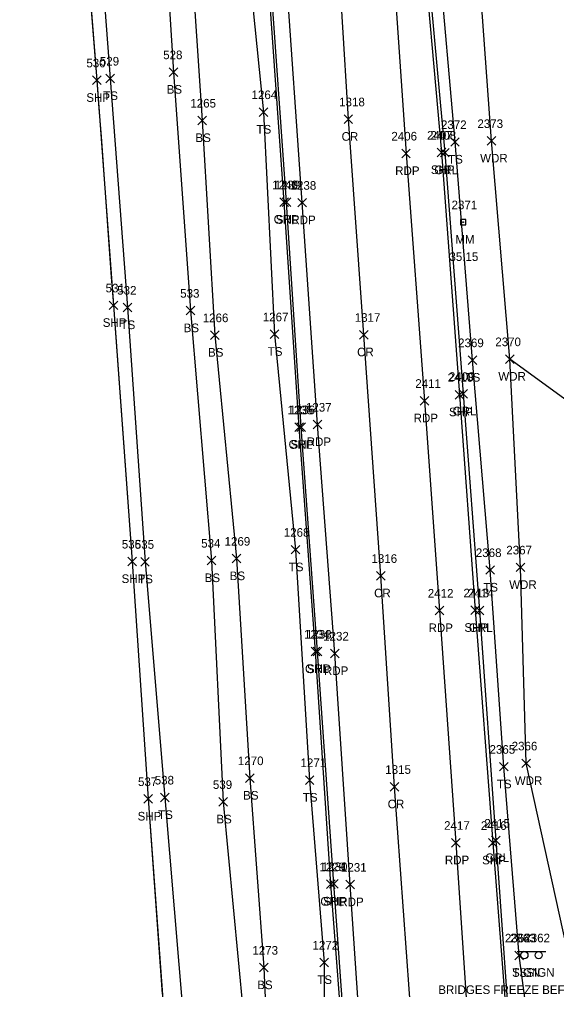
# Model space of a CAD drawing. Extents: x 1650221 to 1650634, y 244606 to 249996.
# Drawn here: x 1650231.8 to 1650356.4, y 246819.2 to 247044.4 of the extents above; entities that cross this region are included whole.
import ezdxf

# ---------------------------------------------------------------- set-up
doc = ezdxf.new("R2010")
doc.units = 0
for name, color, linetype in [('L_A', 7, 'Continuous'), ('L_I', 7, 'Continuous'), ('L_TIC', 7, 'Continuous'), ('LAWA', 7, 'Continuous'), ('LELB', 7, 'Continuous'), ('LSOGP', 7, 'Continuous'), ('P_A', 7, 'Continuous'), ('P_I', 7, 'Continuous'), ('P_TIC', 7, 'Continuous'), ('PET', 7, 'Continuous'), ('PRC', 7, 'Continuous'), ('PSP', 7, 'Continuous'), ('R_A', 7, 'Continuous'), ('R_I', 7, 'Continuous'), ('R_TIC', 7, 'Continuous'), ('RGR', 7, 'Continuous'), ('S_A', 7, 'Continuous'), ('S_C', 7, 'Continuous'), ('S_I', 7, 'Continuous'), ('SRM', 7, 'Continuous'), ('SSGN', 7, 'Continuous')]:
    doc.layers.add(name, color=color, linetype=linetype)

msp = doc.modelspace()

# ---------------------------------------------------------------- linework, layer by layer
at = {"layer": 'L_TIC'}
for points in [[(1650251.85, 247029.65), (1650253.85, 247031.65)], [(1650253.85, 247029.65), (1650251.85, 247031.65)], [(1650266.53, 247031.12), (1650268.53, 247033.12)], [(1650268.53, 247031.12), (1650266.53, 247033.12)], [(1650287.39, 247021.86), (1650289.39, 247023.86)], [(1650289.39, 247021.86), (1650287.39, 247023.86)], [(1650273.2, 247019.9), (1650275.2, 247021.9)], [(1650275.2, 247019.9), (1650273.2, 247021.9)], [(1650331.82, 247014.91), (1650333.82, 247016.91)], [(1650333.82, 247014.91), (1650331.82, 247016.91)], [(1650340.28, 247015.15), (1650342.28, 247017.15)], [(1650342.28, 247015.15), (1650340.28, 247017.15)], [(1650255.86, 246976.49), (1650257.86, 246978.49)], [(1650257.86, 246976.49), (1650255.86, 246978.49)], [(1650270.47, 246975.78), (1650272.47, 246977.78)], [(1650272.47, 246975.78), (1650270.47, 246977.78)], [(1650276.12, 246970.1), (1650278.12, 246972.1)], [(1650278.12, 246970.1), (1650276.12, 246972.1)], [(1650290, 246970.3), (1650292, 246972.3)], [(1650292, 246970.3), (1650290, 246972.3)], [(1650335.85, 246964.3), (1650337.85, 246966.3)], [(1650337.85, 246964.3), (1650335.85, 246966.3)], [(1650344.5, 246964.53), (1650346.5, 246966.53)], [(1650346.5, 246964.53), (1650344.5, 246966.53)], [(1650294.86, 246920.31), (1650296.86, 246922.31)], [(1650296.86, 246920.31), (1650294.86, 246922.31)], [(1650259.95, 246917.52), (1650261.95, 246919.52)], [(1650261.95, 246917.52), (1650259.95, 246919.52)], [(1650275.33, 246917.79), (1650277.33, 246919.79)], [(1650277.33, 246917.79), (1650275.33, 246919.79)], [(1650281.14, 246918.24), (1650283.14, 246920.24)], [(1650283.14, 246918.24), (1650281.14, 246920.24)], [(1650339.96, 246915.6), (1650341.96, 246917.6)], [(1650341.96, 246915.6), (1650339.96, 246917.6)], [(1650347.02, 246916.21), (1650349.02, 246918.21)], [(1650349.02, 246916.21), (1650347.02, 246918.21)], [(1650343.12, 246869.96), (1650345.12, 246871.96)], [(1650345.12, 246869.96), (1650343.12, 246871.96)], [(1650348.32, 246870.74), (1650350.32, 246872.74)], [(1650350.32, 246870.74), (1650348.32, 246872.74)], [(1650284.26, 246867.32), (1650286.26, 246869.32)], [(1650286.26, 246867.32), (1650284.26, 246869.32)], [(1650298.12, 246866.86), (1650300.12, 246868.86)], [(1650300.12, 246866.86), (1650298.12, 246868.86)], [(1650264.57, 246862.83), (1650266.57, 246864.83)], [(1650266.57, 246862.83), (1650264.57, 246864.83)], [(1650278.06, 246861.8), (1650280.06, 246863.8)], [(1650280.06, 246861.8), (1650278.06, 246863.8)], [(1650346.7, 246826.18), (1650348.7, 246828.18)], [(1650348.7, 246826.18), (1650346.7, 246828.18)], [(1650287.53, 246823.34), (1650289.53, 246825.34)], [(1650289.53, 246823.34), (1650287.53, 246825.34)], [(1650301.48, 246824.54), (1650303.48, 246826.54)], [(1650303.48, 246824.54), (1650301.48, 246826.54)]]:
    msp.add_lwpolyline(points, dxfattribs=at)
at = {"layer": 'LAWA'}
msp.add_lwpolyline([(1650378.2, 246794.91), (1650374.9, 246794.97), (1650368.73, 246802.01), (1650359.68, 246824.66), (1650349.32, 246871.74), (1650348.02, 246917.21), (1650345.5, 246965.53), (1650341.28, 247016.15), (1650338.12, 247059.96), (1650335.1, 247106.89), (1650329.41, 247153.66), (1650323.25, 247198.71), (1650318.64, 247242.09)], dxfattribs=at)
at = {"layer": 'LELB'}
for points in [[(1650352.21, 246793.58), (1650347.7, 246827.18), (1650344.12, 246870.96), (1650340.96, 246916.6), (1650336.85, 246965.3), (1650332.82, 247015.91), (1650329.05, 247059.02), (1650324.85, 247105.51), (1650319.65, 247154.56), (1650316.08, 247197.42), (1650310.27, 247244.37)], [(1650242.27, 247235.36), (1650241.91, 247206.66), (1650243.27, 247168.76), (1650246.51, 247128.17), (1650248.83, 247083.97), (1650252.85, 247030.65), (1650256.86, 246977.49), (1650260.95, 246918.52), (1650265.57, 246863.83), (1650269.89, 246812.16), (1650273.23, 246757.17), (1650276.03, 246723.56), (1650279.21, 246672.89), (1650281.34, 246632.54), (1650285.04, 246583.81), (1650287.41, 246538.25), (1650291.5, 246485.31), (1650295.53, 246435.79), (1650299.48, 246380.33), (1650302.27, 246339.43), (1650306.13, 246294.16), (1650309.79, 246242.03)], [(1650273.32, 247234.99), (1650275.56, 247178.37), (1650280.16, 247126.65), (1650283.32, 247073.18), (1650288.39, 247022.86), (1650291, 246971.3), (1650295.86, 246921.31), (1650299.12, 246867.86), (1650302.48, 246825.54), (1650302.49, 246790.4)], [(1650254.94, 247226.35), (1650251.19, 247207.91), (1650256.12, 247169.21), (1650259.77, 247133.43), (1650260.76, 247116.75), (1650264.32, 247083.63), (1650267.53, 247032.12), (1650271.47, 246976.78), (1650276.33, 246918.79), (1650279.06, 246862.8), (1650283.73, 246813.9), (1650289.01, 246756.82), (1650289.41, 246725.67), (1650289.28, 246672.86), (1650289.57, 246632.6), (1650292.55, 246585.88), (1650294.65, 246538.84), (1650297.54, 246482.61), (1650299.6, 246436.73), (1650304.05, 246378.94), (1650306.26, 246339.81), (1650313.05, 246293.73), (1650316.43, 246243)], [(1650258.46, 247225.14), (1650261.39, 247178.96), (1650264.81, 247125.04), (1650270.68, 247074.02), (1650274.2, 247020.9), (1650277.12, 246971.1), (1650282.14, 246919.24), (1650285.26, 246868.32), (1650288.53, 246824.34), (1650289.93, 246790.87)]]:
    msp.add_lwpolyline(points, dxfattribs=at)
at = {"layer": 'LSOGP'}
for points in [[(1650460.29, 246812.05), (1650460.05, 246825.27), (1650459.82, 246827.21), (1650458.97, 246845.05), (1650458.12, 246853.65), (1650457.47, 246862.18), (1650455.2, 246898.26), (1650452.05, 246939.34), (1650409.31, 246929.32), (1650407.32, 246929.28), (1650399.27, 246929.56), (1650394.2, 246930.11), (1650345.5, 246965.53), (1650341.28, 247016.15), (1650338.12, 247059.96)], [(1650248.19, 247050.39), (1650248.73, 247043.67), (1650249.27, 247036.94), (1650249.81, 247030.22), (1650250.28, 247023.69), (1650250.76, 247017.17), (1650251.24, 247010.64), (1650251.71, 247004.11), (1650252.19, 246997.59), (1650252.66, 246991.06), (1650253.14, 246984.54), (1650253.62, 246978.01), (1650254.16, 246970.58), (1650254.71, 246963.15), (1650255.25, 246955.72), (1650255.8, 246948.29), (1650256.34, 246940.87), (1650256.89, 246933.44), (1650257.43, 246926.01), (1650257.98, 246918.58), (1650258.44, 246911.69), (1650258.9, 246904.8), (1650259.37, 246897.91), (1650259.83, 246891.02), (1650260.3, 246884.13), (1650260.76, 246877.24), (1650261.23, 246870.35), (1650261.69, 246863.47), (1650262.16, 246857), (1650262.63, 246850.53), (1650263.09, 246844.06), (1650263.56, 246837.59), (1650264.03, 246831.12), (1650264.49, 246824.65), (1650264.96, 246818.18)]]:
    msp.add_lwpolyline(points, dxfattribs=at)
at = {"layer": 'P_TIC'}
for points in [[(1650248.81, 247029.22), (1650250.81, 247031.22)], [(1650250.81, 247029.22), (1650248.81, 247031.22)], [(1650307.09, 247020.19), (1650309.09, 247022.19)], [(1650309.09, 247020.19), (1650307.09, 247022.19)], [(1650320.46, 247012.25), (1650322.46, 247014.25)], [(1650322.46, 247012.25), (1650320.46, 247014.25)], [(1650328.68, 247012.47), (1650330.68, 247014.47)], [(1650330.68, 247012.47), (1650328.68, 247014.47)], [(1650292.72, 247000.93), (1650294.72, 247002.93)], [(1650294.72, 247000.93), (1650292.72, 247002.93)], [(1650296.4, 247000.83), (1650298.4, 247002.83)], [(1650298.4, 247000.83), (1650296.4, 247002.83)], [(1650252.62, 246977.01), (1650254.62, 246979.01)], [(1650254.62, 246977.01), (1650252.62, 246979.01)], [(1650310.69, 246970.18), (1650312.69, 246972.18)], [(1650312.69, 246970.18), (1650310.69, 246972.18)], [(1650332.89, 246956.27), (1650334.89, 246958.27)], [(1650334.89, 246956.27), (1650332.89, 246958.27)], [(1650324.74, 246954.86), (1650326.74, 246956.86)], [(1650326.74, 246954.86), (1650324.74, 246956.86)], [(1650296.16, 246948.75), (1650298.16, 246950.75)], [(1650298.16, 246948.75), (1650296.16, 246950.75)], [(1650299.96, 246949.35), (1650301.96, 246951.35)], [(1650301.96, 246949.35), (1650299.96, 246951.35)], [(1650256.98, 246917.58), (1650258.98, 246919.58)], [(1650258.98, 246917.58), (1650256.98, 246919.58)], [(1650314.63, 246914.25), (1650316.63, 246916.25)], [(1650316.63, 246914.25), (1650314.63, 246916.25)], [(1650328.2, 246906.19), (1650330.2, 246908.19)], [(1650330.2, 246906.19), (1650328.2, 246908.19)], [(1650336.47, 246906.25), (1650338.47, 246908.25)], [(1650338.47, 246906.25), (1650336.47, 246908.25)], [(1650299.95, 246896.67), (1650301.95, 246898.67)], [(1650301.95, 246896.67), (1650299.95, 246898.67)], [(1650303.95, 246896.23), (1650305.95, 246898.23)], [(1650305.95, 246896.23), (1650303.95, 246898.23)], [(1650317.78, 246865.3), (1650319.78, 246867.3)], [(1650319.78, 246865.3), (1650317.78, 246867.3)], [(1650260.69, 246862.47), (1650262.69, 246864.47)], [(1650262.69, 246862.47), (1650260.69, 246864.47)], [(1650331.99, 246852.31), (1650333.99, 246854.31)], [(1650333.99, 246852.31), (1650331.99, 246854.31)], [(1650340.57, 246852.3), (1650342.57, 246854.3)], [(1650342.57, 246852.3), (1650340.57, 246854.3)], [(1650303.71, 246842.75), (1650305.71, 246844.75)], [(1650305.71, 246842.75), (1650303.71, 246844.75)], [(1650307.51, 246842.59), (1650309.51, 246844.59)], [(1650309.51, 246842.59), (1650307.51, 246844.59)]]:
    msp.add_lwpolyline(points, dxfattribs=at)
at = {"layer": 'PET'}
for points in [[(1650303.59, 247255.04), (1650306.81, 247216.14), (1650310.51, 247167.04), (1650313.87, 247117.51), (1650317.79, 247067.14), (1650321.46, 247013.25), (1650325.74, 246955.86), (1650329.2, 246907.19), (1650332.99, 246853.31), (1650336.64, 246798.8), (1650340.79, 246743.67), (1650343.55, 246701.32), (1650346.09, 246667.41)], [(1650353.63, 246221.52), (1650350.67, 246260.72), (1650347.78, 246301.59), (1650344.6, 246348.96), (1650342.99, 246369.43), (1650339.44, 246417.63), (1650336.53, 246459.1), (1650332.81, 246507), (1650329.1, 246556.8), (1650325.84, 246602.52), (1650321.75, 246661.01), (1650317.87, 246717.27), (1650314.55, 246761.47), (1650311.27, 246802.48), (1650308.51, 246843.59), (1650304.95, 246897.23), (1650300.96, 246950.35), (1650297.4, 247001.83), (1650293.63, 247056.22), (1650290.13, 247106.77), (1650285.97, 247166.23), (1650282.75, 247212.34), (1650279.98, 247248.95)]]:
    msp.add_lwpolyline(points, dxfattribs=at)
at = {"layer": 'PRC'}
msp.add_lwpolyline([(1650365.1, 246222.23), (1650362.04, 246265.67), (1650358.21, 246317.53), (1650354.88, 246368.98), (1650350.4, 246428.86), (1650346.57, 246483.13), (1650341.97, 246537.02), (1650338.57, 246591.04), (1650334.55, 246647.32), (1650330.72, 246698.07), (1650326.82, 246753.45), (1650322.93, 246808.73), (1650318.78, 246866.3), (1650315.63, 246915.25), (1650311.69, 246971.18), (1650308.09, 247021.19), (1650305.21, 247068.94), (1650301.6, 247120.36), (1650298.8, 247160.8), (1650294.82, 247207.2), (1650291.45, 247257.79)], dxfattribs=at)
at = {"layer": 'PSP'}
for points in [[(1650231.83, 247264.44), (1650236.38, 247206.75), (1650239.4, 247169.19), (1650242.51, 247127.54), (1650245.5, 247084.02), (1650249.81, 247030.22), (1650253.62, 246978.01), (1650257.98, 246918.58), (1650261.69, 246863.47), (1650265.43, 246811.71), (1650269.36, 246757.46), (1650271.77, 246723.3), (1650275.43, 246673.04), (1650278.75, 246632.2), (1650282.06, 246584.21), (1650285.45, 246538.51), (1650289.06, 246485.48), (1650292.63, 246435.74), (1650296.7, 246380.37), (1650299.48, 246339.42), (1650302.95, 246294.11), (1650306.82, 246242.11)], [(1650349.68, 246222.04), (1650346.67, 246260.34), (1650343.46, 246301.15), (1650340.56, 246349.22), (1650338.99, 246369.3), (1650335.68, 246417.66), (1650332.87, 246458.75), (1650329.36, 246506.58), (1650325.51, 246556.6), (1650322.14, 246602.26), (1650317.67, 246660.67), (1650313.65, 246716.62), (1650310.76, 246760.87), (1650307.66, 246803.03), (1650304.71, 246843.75), (1650300.95, 246897.67), (1650297.16, 246949.75), (1650293.72, 247001.93), (1650289.97, 247055.55), (1650286.03, 247107.65), (1650281.83, 247165.68), (1650278.51, 247212.85), (1650276.66, 247249.86)], [(1650307.74, 247242.22), (1650310.23, 247216.37), (1650315.19, 247167.56), (1650319.94, 247117.42), (1650324.85, 247068), (1650329.68, 247013.47), (1650333.89, 246957.27), (1650337.47, 246907.25), (1650341.57, 246853.3), (1650345.82, 246798.32), (1650349.51, 246744.26), (1650352.38, 246701.38), (1650355.13, 246668.21)]]:
    msp.add_lwpolyline(points, dxfattribs=at)
at = {"layer": 'R_TIC'}
for points in [[(1650329.46, 247012.43), (1650331.46, 247014.43)], [(1650331.46, 247012.43), (1650329.46, 247014.43)], [(1650292.23, 247000.96), (1650294.23, 247002.96)], [(1650294.23, 247000.96), (1650292.23, 247002.96)], [(1650333.74, 246956.48), (1650335.74, 246958.48)], [(1650335.74, 246956.48), (1650333.74, 246958.48)], [(1650295.68, 246948.72), (1650297.68, 246950.72)], [(1650297.68, 246948.72), (1650295.68, 246950.72)], [(1650337.49, 246906.23), (1650339.49, 246908.23)], [(1650339.49, 246906.23), (1650337.49, 246908.23)], [(1650299.5, 246896.69), (1650301.5, 246898.69)], [(1650301.5, 246896.69), (1650299.5, 246898.69)], [(1650341.31, 246852.82), (1650343.31, 246854.82)], [(1650343.31, 246852.82), (1650341.31, 246854.82)], [(1650303.06, 246842.7), (1650305.06, 246844.7)], [(1650305.06, 246842.7), (1650303.06, 246844.7)]]:
    msp.add_lwpolyline(points, dxfattribs=at)
at = {"layer": 'RGR'}
for points in [[(1650306.3, 246761.34), (1650307.52, 246782.05), (1650307.39, 246800.41), (1650304.06, 246843.7), (1650300.5, 246897.69), (1650296.68, 246949.72), (1650293.23, 247001.96), (1650289.46, 247055.48), (1650285.68, 247107.62), (1650281.2, 247166), (1650278.21, 247212.92), (1650276.32, 247247.97)], [(1650308.18, 247241.07), (1650310.55, 247216.53), (1650315.55, 247167.77), (1650320.43, 247117.51), (1650325.42, 247068.18), (1650330.46, 247013.43), (1650334.74, 246957.48), (1650338.49, 246907.23), (1650342.31, 246853.82), (1650346.19, 246798.3), (1650349.87, 246744.52), (1650353.37, 246701.53), (1650355.68, 246682.24), (1650357.83, 246668.94)]]:
    msp.add_lwpolyline(points, dxfattribs=at)
at = {"layer": 'SRM'}
for p, q in [((1650335.36, 246997.95), (1650334.11, 246997.95)), ((1650334.11, 246997.95), (1650334.11, 246996.7)), ((1650335.36, 246997.95), (1650334.11, 246997.95)), ((1650334.11, 246997.95), (1650334.11, 246996.7)), ((1650335.36, 246996.7), (1650335.36, 246997.95)), ((1650335.36, 246996.7), (1650335.36, 246997.95)), ((1650334.11, 246996.7), (1650335.36, 246996.7)), ((1650334.11, 246996.7), (1650335.36, 246996.7))]:
    msp.add_line(p, q, dxfattribs=at)
msp.add_circle((1650334.71, 246997.29), 0.0833, dxfattribs=at)
at = {"layer": 'SSGN'}
for p, q in [((1650347.26, 246828.06), (1650350.59, 246828.06)), ((1650348.9, 246827.22), (1650348.9, 246827.22)), ((1650350.57, 246828.06), (1650353.91, 246828.06)), ((1650352.22, 246827.23), (1650352.22, 246827.23))]:
    msp.add_line(p, q, dxfattribs=at)
for centre in [(1650348.9, 246827.22), (1650352.22, 246827.23)]:
    msp.add_circle(centre, 0.833, dxfattribs=at)

# ---------------------------------------------------------------- texts
at = {"layer": 'L_A'}
for s, p in [('TS', (1650251.26, 247025.65)), ('BS', (1650265.97, 247027.12)), ('TS', (1650286.8, 247017.86)), ('BS', (1650272.64, 247015.9)), ('TS', (1650331.22, 247010.91)), ('WDR', (1650338.65, 247011.15)), ('TS', (1650255.27, 246972.49)), ('BS', (1650269.91, 246971.78)), ('BS', (1650275.56, 246966.1)), ('TS', (1650289.41, 246966.3)), ('TS', (1650335.26, 246960.3)), ('WDR', (1650342.86, 246960.53)), ('TS', (1650294.27, 246916.31)), ('TS', (1650259.36, 246913.52)), ('BS', (1650274.78, 246913.79)), ('BS', (1650280.59, 246914.24)), ('TS', (1650339.37, 246911.6)), ('WDR', (1650345.38, 246912.21)), ('TS', (1650342.53, 246865.96)), ('WDR', (1650346.68, 246866.74)), ('BS', (1650283.7, 246863.32)), ('TS', (1650297.53, 246862.86)), ('TS', (1650263.98, 246858.83)), ('BS', (1650277.5, 246857.8)), ('TS', (1650300.89, 246820.54)), ('TS', (1650346.1, 246822.18)), ('BS', (1650286.97, 246819.34))]:
    msp.add_text(s, height=2, dxfattribs=at).set_placement(p)
at = {"layer": 'L_I'}
for s, p in [('528', (1650265.16, 247035.12)), ('529', (1650250.48, 247033.65)), ('1264', (1650285.65, 247025.86)), ('1265', (1650271.46, 247023.9)), ('2372', (1650329.56, 247018.91)), ('2373', (1650338.02, 247019.15)), ('532', (1650254.5, 246980.49)), ('533', (1650269.11, 246979.78)), ('1266', (1650274.33, 246974.1)), ('1267', (1650288.26, 246974.3)), ('2369', (1650333.54, 246968.3)), ('2370', (1650342.16, 246968.53)), ('1268', (1650293.12, 246924.31)), ('535', (1650258.59, 246921.52)), ('534', (1650273.97, 246921.79)), ('1269', (1650279.4, 246922.24)), ('2368', (1650337.65, 246919.6)), ('2367', (1650344.71, 246920.21)), ('2366', (1650345.96, 246874.74)), ('2365', (1650340.82, 246873.96)), ('1270', (1650282.48, 246871.32)), ('1271', (1650297, 246870.86)), ('538', (1650263.2, 246866.83)), ('539', (1650276.69, 246865.8)), ('2364', (1650344.39, 246830.18)), ('1273', (1650285.84, 246827.34)), ('1272', (1650299.78, 246828.54))]:
    msp.add_text(s, height=2, dxfattribs=at).set_placement(p)
at = {"layer": 'P_A'}
for s, p in [('SHP', (1650247.34, 247025.22)), ('CR', (1650306.52, 247016.19)), ('RDP', (1650318.95, 247008.25)), ('SHP', (1650327.22, 247008.47)), ('SHP', (1650291.26, 246996.93)), ('RDP', (1650294.88, 246996.83)), ('SHP', (1650251.15, 246973.01)), ('CR', (1650310.12, 246966.18)), ('RDP', (1650323.23, 246950.86)), ('SHP', (1650331.43, 246952.27)), ('SHP', (1650294.69, 246944.75)), ('RDP', (1650298.44, 246945.35)), ('SHP', (1650255.51, 246913.58)), ('CR', (1650314.06, 246910.25)), ('RDP', (1650326.69, 246902.19)), ('SHP', (1650335, 246902.25)), ('SHP', (1650298.49, 246892.67)), ('RDP', (1650302.43, 246892.23)), ('CR', (1650317.21, 246861.3)), ('SHP', (1650259.23, 246858.47)), ('RDP', (1650330.47, 246848.31)), ('SHP', (1650339.11, 246848.3)), ('SHP', (1650302.25, 246838.75)), ('RDP', (1650306, 246838.59))]:
    msp.add_text(s, height=2, dxfattribs=at).set_placement(p)
at = {"layer": 'P_I'}
for s, p in [('530', (1650247.36, 247033.22)), ('1318', (1650305.96, 247024.19)), ('2406', (1650318.07, 247016.25)), ('2407', (1650326.34, 247016.47)), ('1239', (1650291.02, 247004.93)), ('1238', (1650294.7, 247004.83)), ('531', (1650251.82, 246981.01)), ('1317', (1650309.57, 246974.18)), ('2410', (1650331.11, 246960.27)), ('2411', (1650323.61, 246958.86)), ('1237', (1650298.26, 246953.35)), ('1236', (1650294.41, 246952.75)), ('536', (1650255.56, 246921.58)), ('1316', (1650313.45, 246918.25)), ('2412', (1650326.51, 246910.19)), ('2413', (1650334.78, 246910.25)), ('1233', (1650298.26, 246900.67)), ('1232', (1650302.25, 246900.23)), ('1315', (1650316.65, 246869.3)), ('537', (1650259.33, 246866.47)), ('2417', (1650330.29, 246856.31)), ('2416', (1650338.82, 246856.3)), ('1230', (1650301.93, 246846.75)), ('1231', (1650306.39, 246846.59))]:
    msp.add_text(s, height=2, dxfattribs=at).set_placement(p)
at = {"layer": 'R_A'}
for p in [(1650328.01, 247008.43), (1650290.78, 246996.96), (1650332.28, 246952.48), (1650294.23, 246944.72), (1650336.03, 246902.23), (1650298.05, 246892.69), (1650339.85, 246848.82), (1650301.6, 246838.7)]:
    msp.add_text('GRL', height=2, dxfattribs=at).set_placement(p)
at = {"layer": 'R_I'}
for s, p in [('2408', (1650327.13, 247016.43)), ('1240', (1650290.45, 247004.96)), ('2409', (1650331.39, 246960.48)), ('1235', (1650293.99, 246952.72)), ('2414', (1650335.8, 246910.23)), ('1234', (1650297.81, 246900.69)), ('2415', (1650339.62, 246856.82)), ('1229', (1650301.36, 246846.7))]:
    msp.add_text(s, height=2, dxfattribs=at).set_placement(p)
at = {"layer": 'S_A'}
for s, p in [('MM', (1650332.9, 246992.3)), ('SIGN', (1650346.04, 246822.2)), ('SIGN', (1650349.36, 246822.21))]:
    msp.add_text(s, height=2, dxfattribs=at).set_placement(p)
at = {"layer": 'S_C'}
for s, p in [('35.15', (1650331.53, 246988.3)), ('BRIDGES FREEZE BEFORE ROAD', (1650328.95, 246818.21))]:
    msp.add_text(s, height=2, dxfattribs=at).set_placement(p)
at = {"layer": 'S_I'}
for s, p in [('2371', (1650332.02, 247000.3)), ('2363', (1650345.58, 246830.2)), ('2362', (1650348.89, 246830.21))]:
    msp.add_text(s, height=2, dxfattribs=at).set_placement(p)

doc.saveas('drawing.dxf')
